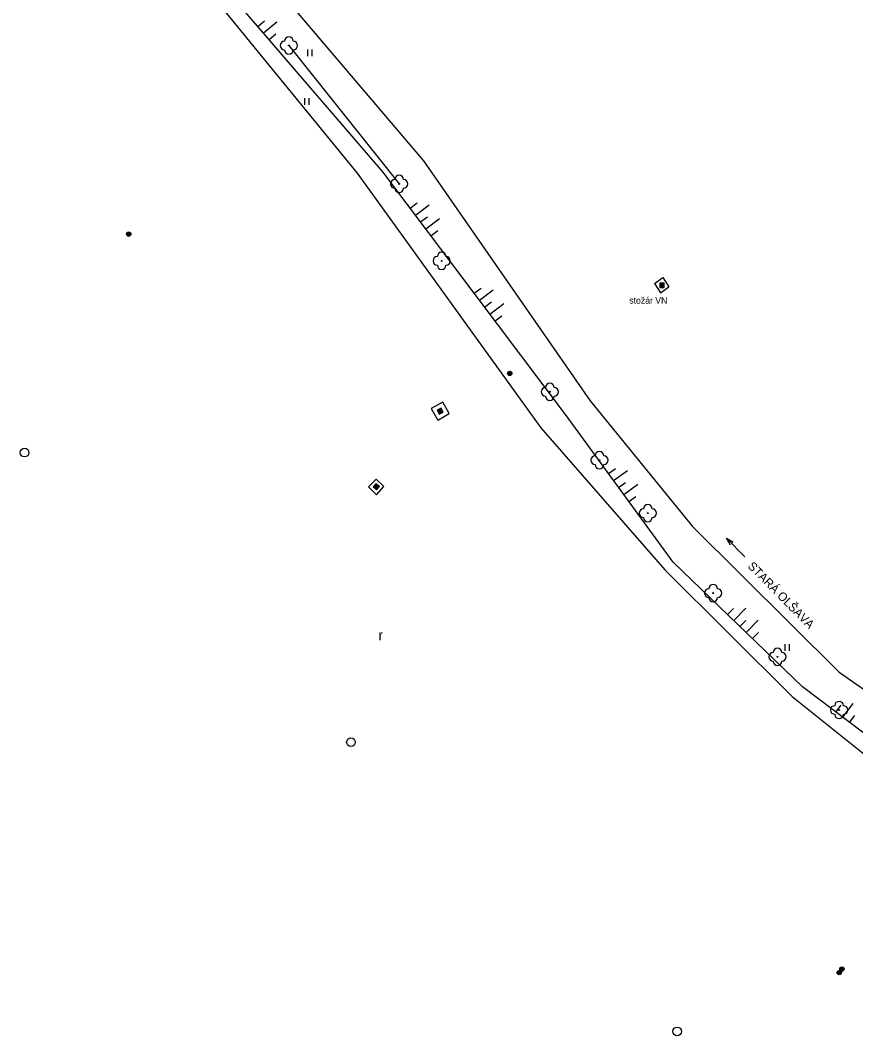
# Model space of a CAD drawing. Extents: x -539515 to -538098, y -1182060 to -1180157.
# Drawn here: x -538952.2 to -538855.7, y -1181625.6 to -1181508.2 of the extents above; entities that cross this region are included whole.
import ezdxf

# ---------------------------------------------------------------- set-up
doc = ezdxf.new("R2010")
doc.units = 0
for name, color, linetype in [('Vrstva 13', 7, 'Continuous'), ('Vrstva 21', 7, 'Continuous'), ('Vrstva 22', 7, 'Continuous'), ('Vrstva 23', 7, 'Continuous'), ('Vrstva 25', 7, 'Continuous'), ('Vrstva 27', 7, 'Continuous'), ('Vrstva 29', 7, 'Continuous'), ('Vrstva 36', 7, 'Continuous'), ('Vrstva 41', 7, 'Continuous'), ('Vrstva 45', 7, 'Continuous'), ('Vrstva 68', 7, 'Continuous')]:
    doc.layers.add(name, color=color, linetype=linetype)

msp = doc.modelspace()

# ---------------------------------------------------------------- linework, layer by layer
at = {"layer": 'Vrstva 13'}
for p, q in [((-538878.922, -1181538.598), (-538877.96, -1181537.909)), ((-538878.922, -1181538.598), (-538878.22, -1181539.686)), ((-538877.96, -1181537.909), (-538877.258, -1181538.997)), ((-538878.22, -1181539.686), (-538877.258, -1181538.997))]:
    msp.add_line(p, q, dxfattribs=at)
at = {"layer": 'Vrstva 21'}
msp.add_lwpolyline([(-538921.17, -1181511.09), (-538908.43, -1181527.1)], dxfattribs=at)
at = {"layer": 'Vrstva 22'}
for centre in [(-538921.17, -1181511.09), (-538908.43, -1181527.1), (-538903.52, -1181536), (-538891.01, -1181551.12), (-538885.29, -1181559.03), (-538879.7, -1181565.15), (-538872.13, -1181574.39), (-538864.7, -1181581.76), (-538857.59, -1181587.91)]:
    msp.add_circle(centre, 0.05, dxfattribs=at)
for centre, start, end in [((-538921.17, -1181510.59), 0, 180), ((-538921.67, -1181511.09), 90, 270), ((-538921.17, -1181511.59), 180, 0), ((-538920.67, -1181511.09), 270, 90), ((-538908.93, -1181527.1), 90, 270), ((-538908.43, -1181526.6), 0, 180), ((-538907.93, -1181527.1), 270, 90), ((-538908.43, -1181527.6), 180, 0), ((-538903.52, -1181535.5), 0, 180), ((-538904.02, -1181536), 90, 270), ((-538903.02, -1181536), 270, 90), ((-538903.52, -1181536.5), 180, 0), ((-538891.01, -1181550.62), 0, 180), ((-538891.51, -1181551.12), 90, 270), ((-538890.51, -1181551.12), 270, 90), ((-538891.01, -1181551.62), 180, 0), ((-538885.79, -1181559.03), 90, 270), ((-538885.29, -1181558.53), 0, 180), ((-538884.79, -1181559.03), 270, 90), ((-538885.29, -1181559.53), 180, 0), ((-538879.7, -1181564.65), 0, 180), ((-538880.2, -1181565.15), 90, 270), ((-538879.7, -1181565.65), 180, 0), ((-538879.2, -1181565.15), 270, 90), ((-538872.63, -1181574.39), 90, 270), ((-538872.13, -1181573.89), 0, 180), ((-538871.63, -1181574.39), 270, 90), ((-538872.13, -1181574.89), 180, 0), ((-538864.7, -1181581.26), 0, 180), ((-538865.2, -1181581.76), 90, 270), ((-538864.2, -1181581.76), 270, 90), ((-538864.7, -1181582.26), 180, 0), ((-538858.09, -1181587.91), 90, 270), ((-538857.59, -1181587.41), 0, 180), ((-538857.09, -1181587.91), 270, 90), ((-538857.59, -1181588.41), 180, 0)]:
    msp.add_arc(centre, 0.5, start, end, dxfattribs=at)
at = {"layer": 'Vrstva 23'}
for p, q in [((-538929.88, -1181505.52), (-538913.28, -1181525.86)), ((-538913.28, -1181525.86), (-538892.04, -1181555.28)), ((-538892.04, -1181555.28), (-538877.71, -1181571.72)), ((-538877.71, -1181571.72), (-538863.02, -1181586.35)), ((-538863.02, -1181586.35), (-538852.12, -1181595.07))]:
    msp.add_line(p, q, dxfattribs=at)
at = {"layer": 'Vrstva 25'}
for points in [[(-538878.293, -1181539.074), (-538877.793, -1181539.074), (-538877.793, -1181538.574), (-538878.293, -1181538.574)], [(-538878.243, -1181539.024), (-538877.843, -1181539.024), (-538877.843, -1181538.624), (-538878.243, -1181538.624)], [(-538878.193, -1181538.974), (-538877.893, -1181538.974), (-538877.893, -1181538.674), (-538878.193, -1181538.674)], [(-538878.143, -1181538.924), (-538877.943, -1181538.924), (-538877.943, -1181538.724), (-538878.143, -1181538.724)], [(-538878.093, -1181538.874), (-538877.993, -1181538.874), (-538877.993, -1181538.774), (-538878.093, -1181538.774)], [(-538903.796, -1181553.696), (-538903.35, -1181553.47), (-538903.577, -1181553.024), (-538904.023, -1181553.251)], [(-538903.774, -1181553.629), (-538903.418, -1181553.448), (-538903.599, -1181553.091), (-538903.955, -1181553.273)], [(-538903.752, -1181553.562), (-538903.485, -1181553.426), (-538903.621, -1181553.159), (-538903.888, -1181553.295)], [(-538903.73, -1181553.495), (-538903.552, -1181553.404), (-538903.643, -1181553.226), (-538903.821, -1181553.316)], [(-538903.708, -1181553.427), (-538903.619, -1181553.382), (-538903.665, -1181553.293), (-538903.754, -1181553.338)], [(-538911.066, -1181562.448), (-538910.722, -1181562.085), (-538911.086, -1181561.741), (-538911.429, -1181562.105)], [(-538911.068, -1181562.378), (-538910.793, -1181562.087), (-538911.084, -1181561.812), (-538911.358, -1181562.103)], [(-538911.07, -1181562.307), (-538910.864, -1181562.089), (-538911.082, -1181561.883), (-538911.288, -1181562.101)], [(-538911.072, -1181562.236), (-538910.934, -1181562.091), (-538911.08, -1181561.953), (-538911.217, -1181562.099)], [(-538911.074, -1181562.166), (-538911.005, -1181562.093), (-538911.078, -1181562.024), (-538911.146, -1181562.097)]]:
    msp.add_lwpolyline(points, close=True, dxfattribs=at)
for centre, radius in [((-538939.69, -1181532.89), 0.25), ((-538939.69, -1181532.89), 0.2), ((-538939.69, -1181532.89), 0.15), ((-538939.69, -1181532.89), 0.1), ((-538939.69, -1181532.89), 0.05), ((-538895.645, -1181548.997), 0.25), ((-538895.645, -1181548.997), 0.2), ((-538895.645, -1181548.997), 0.15), ((-538895.645, -1181548.997), 0.1), ((-538895.645, -1181548.997), 0.05), ((-538857.568, -1181618.26), 0.25), ((-538857.568, -1181618.26), 0.2), ((-538857.568, -1181618.26), 0.15), ((-538857.568, -1181618.26), 0.1), ((-538857.568, -1181618.26), 0.05), ((-538857.267, -1181617.859), 0.25), ((-538857.267, -1181617.859), 0.2), ((-538857.267, -1181617.859), 0.15), ((-538857.267, -1181617.859), 0.1), ((-538857.267, -1181617.859), 0.05)]:
    msp.add_circle(centre, radius, dxfattribs=at)
at = {"layer": 'Vrstva 27'}
for p, q in [((-538924.758, -1181508.887), (-538923.999, -1181508.236)), ((-538924.107, -1181509.646), (-538922.589, -1181508.343)), ((-538923.455, -1181510.404), (-538922.696, -1181509.753)), ((-538907.163, -1181529.899), (-538906.364, -1181529.298)), ((-538906.561, -1181530.698), (-538904.963, -1181529.495)), ((-538905.96, -1181531.497), (-538905.161, -1181530.896)), ((-538905.359, -1181532.296), (-538903.761, -1181531.093)), ((-538904.757, -1181533.095), (-538903.958, -1181532.494)), ((-538899.755, -1181539.742), (-538898.956, -1181539.141)), ((-538899.153, -1181540.541), (-538897.555, -1181539.338)), ((-538898.552, -1181541.34), (-538897.753, -1181540.739)), ((-538897.951, -1181542.139), (-538896.353, -1181540.936)), ((-538897.349, -1181542.938), (-538896.55, -1181542.337)), ((-538884.239, -1181560.575), (-538883.431, -1181559.987)), ((-538883.651, -1181561.384), (-538882.034, -1181560.206)), ((-538883.062, -1181562.192), (-538882.254, -1181561.603)), ((-538882.473, -1181563), (-538880.857, -1181561.823)), ((-538881.885, -1181563.809), (-538881.076, -1181563.22)), ((-538870.485, -1181576.88), (-538869.791, -1181576.16)), ((-538869.764, -1181577.574), (-538868.377, -1181576.133)), ((-538869.044, -1181578.267), (-538868.351, -1181577.547)), ((-538868.324, -1181578.96), (-538866.937, -1181577.52)), ((-538867.603, -1181579.654), (-538866.91, -1181578.934)), ((-538857.961, -1181588.142), (-538857.358, -1181587.344)), ((-538857.164, -1181588.745), (-538855.957, -1181587.151)), ((-538856.367, -1181589.349), (-538855.763, -1181588.552))]:
    msp.add_line(p, q, dxfattribs=at)
for centre in [(-538951.72, -1181558.16), (-538914, -1181591.62), (-538876.29, -1181625.06)]:
    msp.add_circle(centre, 0.5, dxfattribs=at)
at = {"layer": 'Vrstva 29'}
for p, q in [((-538925.51, -1181501.02), (-538905.63, -1181524.44)), ((-538910.33, -1181525.69), (-538928.8, -1181504.18)), ((-538905.63, -1181524.44), (-538886.36, -1181552.16)), ((-538889.1, -1181553.9), (-538910.33, -1181525.69)), ((-538886.36, -1181552.16), (-538874.51, -1181566.71)), ((-538876.78, -1181570.82), (-538889.1, -1181553.9)), ((-538874.51, -1181566.71), (-538857.56, -1181583.54)), ((-538861.82, -1181585.22), (-538876.78, -1181570.82)), ((-538857.56, -1181583.54), (-538848.65, -1181589.82)), ((-538851.03, -1181593.39), (-538861.82, -1181585.22))]:
    msp.add_line(p, q, dxfattribs=at)
at = {"layer": 'Vrstva 36'}
for p, q in [((-538919.002, -1181512.31), (-538919.002, -1181511.56)), ((-538918.502, -1181512.31), (-538918.502, -1181511.56)), ((-538919.351, -1181517.948), (-538919.351, -1181517.198)), ((-538918.851, -1181517.948), (-538918.851, -1181517.198)), ((-538863.816, -1181581.054), (-538863.816, -1181580.304)), ((-538863.316, -1181581.054), (-538863.316, -1181580.304))]:
    msp.add_line(p, q, dxfattribs=at)
at = {"layer": 'Vrstva 45'}
msp.add_line((-538868.479, -1181570.189), (-538870.588, -1181568.056), dxfattribs=at)
msp.add_lwpolyline([(-538870.136, -1181568.841), (-538870.588, -1181568.056), (-538869.809, -1181568.517)], dxfattribs=at)
at = {"layer": 'Vrstva 68'}
for points in [[(-538904.75, -1181553.06), (-538903.97, -1181554.4), (-538902.66, -1181553.65), (-538903.4, -1181552.31), (-538904.75, -1181553.06)], [(-538911.09, -1181561.23), (-538911.97, -1181562.13), (-538911.06, -1181563.05), (-538910.19, -1181562.06), (-538911.09, -1181561.23)]]:
    msp.add_lwpolyline(points, dxfattribs=at)

# ---------------------------------------------------------------- texts
at = {"layer": 'Vrstva 36'}
msp.add_text('r', height=1.2, dxfattribs=at).set_placement((-538910.834, -1181579.862))
at = {"layer": 'Vrstva 41'}
msp.add_text('stožár VN', height=0.75, dxfattribs=at).set_placement((-538881.838, -1181540.936))
at = {"layer": 'Vrstva 45'}
msp.add_text('STARÁ OLŠAVA', height=1, rotation=314.67294, dxfattribs=at).set_placement((-538868.219, -1181571.366))

doc.saveas('drawing.dxf')
